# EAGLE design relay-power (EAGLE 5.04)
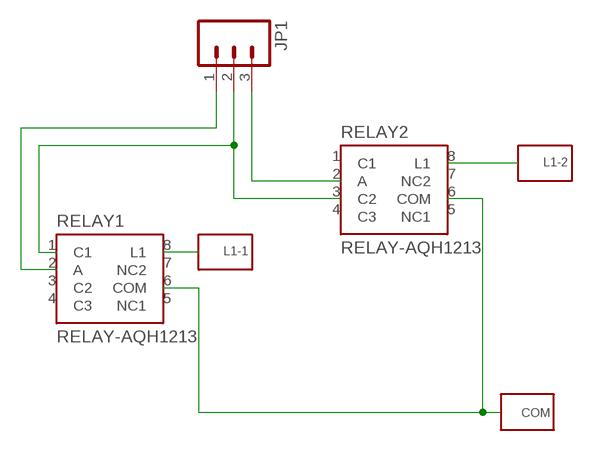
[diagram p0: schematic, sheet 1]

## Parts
COM  WIREPAD-SMD-NO-VALUE  [WIREPAD-SMD]
JP1  M03PTH  [1X03]
L1-1  WIREPAD-SMD-NO-VALUE  [WIREPAD-SMD]
L1-2  WIREPAD-SMD-NO-VALUE  [WIREPAD-SMD]
RELAY1  RELAY-AQH1213  [DIL8-3]
RELAY2  RELAY-AQH1213  [DIL8-3]

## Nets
N$1: JP1.2 RELAY1.1(C1) RELAY2.3(C2)
N$2: JP1.1 RELAY1.2(A)
N$3: JP1.3 RELAY2.2(A)
N$4: COM.1(P) RELAY1.6(COM) RELAY2.6(COM)
N$5: L1-1.1(P) RELAY1.8(L1)
N$6: L1-2.1(P) RELAY2.8(L1)
Unconnected: RELAY1.3(C2) RELAY1.4(C3) RELAY1.5(NC1) RELAY1.7(NC2) RELAY2.1(C1) RELAY2.4(C3) RELAY2.5(NC1) RELAY2.7(NC2)

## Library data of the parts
COM L1-1 L1-2 = trl:WIREPAD-SMD-NO-VALUE
JP1 = SparkFun:M03: Header 3 Standard 3-pin 0.1" header. Use with straight break away headers (SKU : PRT-00116), right angle break away headers (PRT-00553), swiss pins (PRT-00743), machine pins (PRT-00117), and female headers (PRT-00115). Molex polarized connector foot print use with SKU : PRT-08232 with associated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
RELAY1 RELAY2 = trl:RELAY-AQH1213

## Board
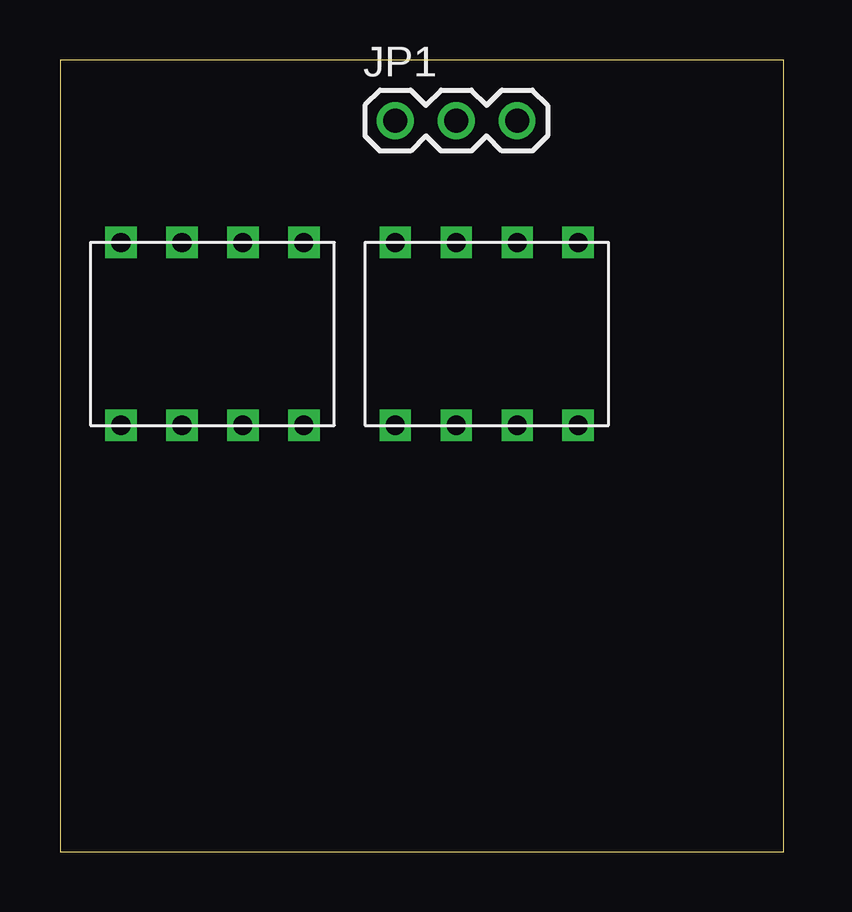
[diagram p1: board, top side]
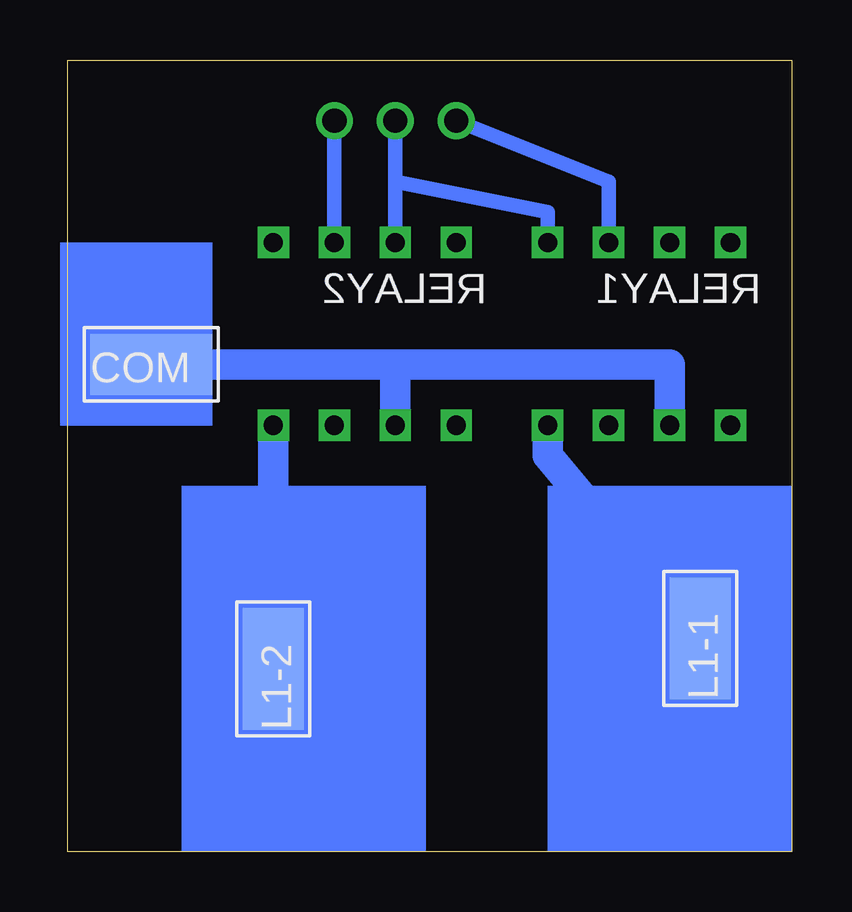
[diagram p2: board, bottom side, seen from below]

Size 30.15 x 33.01 mm. Coordinates in mm from the lower left corner, seen from the top.
Outline: 0,0 30.15,0 30.15,33.01 0,33.01 0,0
Copper layers (1*16): Top 0.035mm / dielectric 1.5mm / Bottom 0.035mm
Design rules "default": minimum track width 10mil, minimum drill 24mil, track to track 8mil, track to pad 8mil, pad to pad 8mil, via to via 8mil, smd to smd 8mil, copper to edge 40mil, drill to drill 8mil, minimum pad ring 10mil, minimum via ring 8mil, stop-mask expansion 4mil, vias tented up to drill 0mil, thermal gap 10mil

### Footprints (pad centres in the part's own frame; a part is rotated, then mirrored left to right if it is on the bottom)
WIREPAD-SMD = smd 2.54 x 5.08: 1 0,0
1X03 = drill 1.016 round: 1 0,0; 2 2.54,0; 3 5.08,0
DIL8-3 = drill 0.8 square: 1 -3.81,3.81; 2 -3.81,1.27; 3 -3.81,-1.27; 4 -3.81,-3.81; 5 3.81,-3.81; 6 3.81,-1.27; 7 3.81,1.27; 8 3.81,3.81

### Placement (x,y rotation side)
COM  26.67,20.32 270 bottom
JP1  13.97,30.48 0 top
L1-1  3.81,8.89 0 bottom
L1-2  21.59,7.62 0 bottom
RELAY1  6.35,21.59 270 top
RELAY2  17.78,21.59 270 top

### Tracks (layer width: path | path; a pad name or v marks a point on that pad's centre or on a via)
N$1
  Bottom 0.61: RELAY1.1 10.16,26.67 16.51,27.94 | 16.51,27.94 RELAY2.3 16.51,27.94 | 16.51,27.94 JP1.2
N$2
  Bottom 0.61: RELAY1.2 7.62,27.94 JP1.1
N$3
  Bottom 0.61: RELAY2.2 JP1.3
N$4
  Bottom 1.27: RELAY1.6 5.08,20.32 16.51,20.32 | 16.51,20.32 COM.1 | 16.51,20.32 RELAY2.6
N$5
  Bottom 1.27: L1-1.1 10.16,16.51 RELAY1.8
N$6
  Bottom 1.27: RELAY2.8 L1-2.1
(copper drawn outside any net)
  shapes: Bottom area x3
